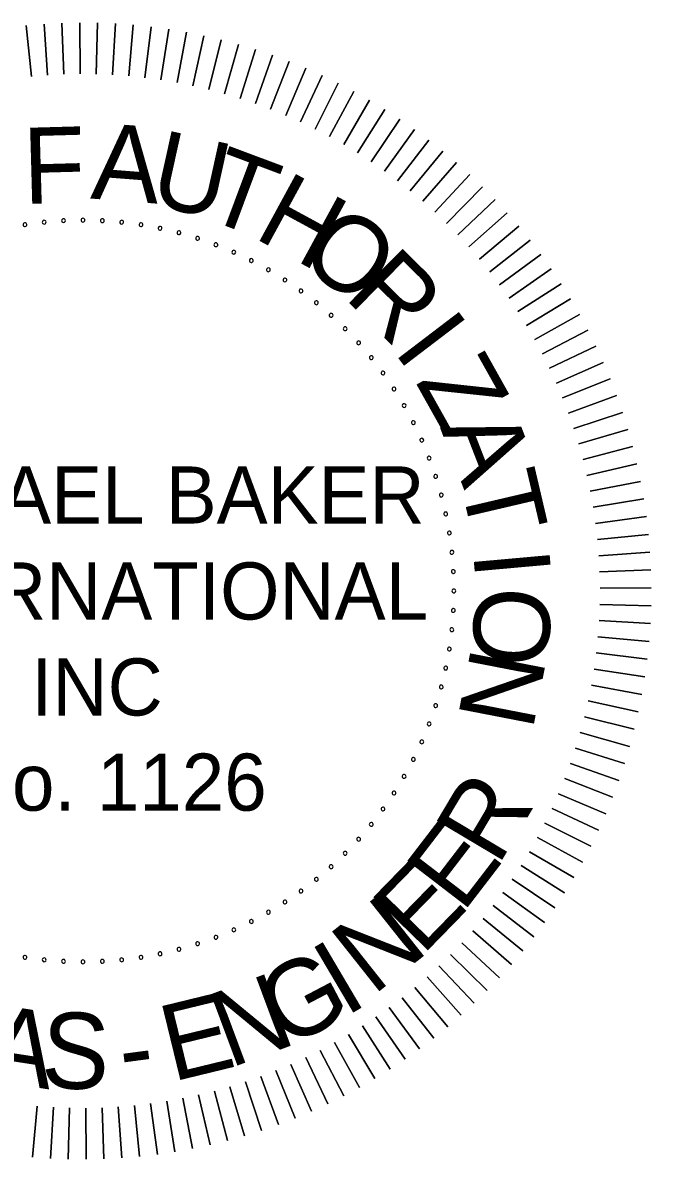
# Model space of a CAD drawing. Extents: x -43543 to 34500, y -13675 to 11152.
# Drawn here: x 7473 to 8849, y -8588 to -6099 of the extents above; entities that cross this region are included whole.
import ezdxf

# ---------------------------------------------------------------- set-up
doc = ezdxf.new("R2010")
doc.units = 0
doc.layers.add('G-ANNO-TEXT', color=7, linetype='Continuous')

msp = doc.modelspace()

# ---------------------------------------------------------------- linework, layer by layer
at = {"layer": 'G-ANNO-TEXT'}
for points in [[(7491.6, -6217.2), (7480.4, -6105.5)], [(7480.4, -6105.5), (7491.6, -6217.2)], [(7527, -6214.2), (7519.4, -6102.2)], [(7519.4, -6102.2), (7527, -6214.2)], [(7562.5, -6212.3), (7558.4, -6100.2)], [(7558.4, -6100.2), (7562.5, -6212.3)], [(7598.1, -6211.6), (7597.5, -6099.4)], [(7597.5, -6099.4), (7598.1, -6211.6)], [(7633.7, -6211.9), (7636.6, -6099.8)], [(7636.6, -6099.8), (7633.7, -6211.9)], [(7669.2, -6213.4), (7675.6, -6101.4)], [(7675.6, -6101.4), (7669.2, -6213.4)], [(7704.7, -6216), (7714.6, -6104.2)], [(7714.6, -6104.2), (7704.7, -6216)], [(7740, -6219.7), (7753.5, -6108.3)], [(7753.5, -6108.3), (7740, -6219.7)], [(7775.3, -6224.5), (7792.2, -6113.6)], [(7792.2, -6113.6), (7775.3, -6224.5)], [(7810.4, -6230.5), (7830.8, -6120.1)], [(7830.8, -6120.1), (7810.4, -6230.5)], [(7845.2, -6237.5), (7869.1, -6127.8)], [(7869.1, -6127.8), (7845.2, -6237.5)], [(7879.9, -6245.6), (7907.2, -6136.7)], [(7907.2, -6136.7), (7879.9, -6245.6)], [(7914.2, -6254.8), (7944.9, -6146.8)], [(7944.9, -6146.8), (7914.2, -6254.8)], [(7948.3, -6265), (7982.4, -6158.1)], [(7982.4, -6158.1), (7948.3, -6265)], [(7982, -6276.4), (8019.4, -6170.6)], [(8019.4, -6170.6), (7982, -6276.4)], [(8015.3, -6288.8), (8056.1, -6184.2)], [(8056.1, -6184.2), (8015.3, -6288.8)], [(8048.3, -6302.2), (8092.3, -6198.9)], [(8092.3, -6198.9), (8048.3, -6302.2)], [(8080.8, -6316.6), (8128, -6214.8)], [(8128, -6214.8), (8080.8, -6316.6)], [(8112.8, -6332.1), (8163.2, -6231.8)], [(8163.2, -6231.8), (8112.8, -6332.1)], [(8144.3, -6348.6), (8197.8, -6249.9)], [(8197.8, -6249.9), (8144.3, -6348.6)], [(8175.3, -6366), (8231.9, -6269.1)], [(8231.9, -6269.1), (8175.3, -6366)], [(8205.7, -6384.4), (8265.3, -6289.4)], [(8265.3, -6289.4), (8205.7, -6384.4)], [(8235.6, -6403.8), (8298.1, -6310.6)], [(8298.1, -6310.6), (8235.6, -6403.8)], [(8264.8, -6424.1), (8330.2, -6332.9)], [(8330.2, -6332.9), (8264.8, -6424.1)], [(8293.3, -6445.3), (8361.6, -6356.2)], [(8361.6, -6356.2), (8293.3, -6445.3)], [(8321.2, -6467.4), (8392.3, -6380.5)], [(8392.3, -6380.5), (8321.2, -6467.4)], [(8348.4, -6490.3), (8422.1, -6405.7)], [(8422.1, -6405.7), (8348.4, -6490.3)], [(8451.2, -6431.9), (8374.8, -6514.1)], [(8374.8, -6514.1), (8451.2, -6431.9)], [(8479.4, -6458.9), (8400.5, -6538.7)], [(8400.5, -6538.7), (8479.4, -6458.9)], [(8506.8, -6486.8), (8425.4, -6564.1)], [(8425.4, -6564.1), (8506.8, -6486.8)], [(8533.3, -6515.6), (8449.5, -6590.3)], [(8449.5, -6590.3), (8533.3, -6515.6)], [(8558.8, -6545.2), (8472.7, -6617.2)], [(8472.7, -6617.2), (8558.8, -6545.2)], [(8583.4, -6575.6), (8495.1, -6644.8)], [(8495.1, -6644.8), (8583.4, -6575.6)], [(8607.1, -6606.7), (8516.6, -6673.2)], [(8516.6, -6673.2), (8607.1, -6606.7)], [(8629.7, -6638.6), (8537.3, -6702.2)], [(8537.3, -6702.2), (8629.7, -6638.6)], [(8651.4, -6671.1), (8556.9, -6731.8)], [(8556.9, -6731.8), (8651.4, -6671.1)], [(8672, -6704.3), (8575.7, -6762)], [(8575.7, -6762), (8672, -6704.3)], [(8691.5, -6738.2), (8593.5, -6792.8)], [(8593.5, -6792.8), (8691.5, -6738.2)], [(8710, -6772.6), (8610.3, -6824.1)], [(8610.3, -6824.1), (8710, -6772.6)], [(8727.4, -6807.6), (8626.1, -6856)], [(8626.1, -6856), (8727.4, -6807.6)], [(8743.7, -6843.2), (8641, -6888.3)], [(8641, -6888.3), (8743.7, -6843.2)], [(8758.9, -6879.2), (8654.7, -6921.1)], [(8654.7, -6921.1), (8758.9, -6879.2)], [(8772.9, -6915.7), (8667.5, -6954.3)], [(8667.5, -6954.3), (8772.9, -6915.7)], [(8785.8, -6952.6), (8679.2, -6987.9)], [(8679.2, -6987.9), (8785.8, -6952.6)], [(8797.5, -6989.9), (8689.9, -7021.8)], [(8689.9, -7021.8), (8797.5, -6989.9)], [(8808, -7027.6), (8699.4, -7056.1)], [(8699.4, -7056.1), (8808, -7027.6)], [(8817.3, -7065.5), (8707.9, -7090.6)], [(8707.9, -7090.6), (8817.3, -7065.5)], [(8825.5, -7103.8), (8715.3, -7125.4)], [(8715.3, -7125.4), (8825.5, -7103.8)], [(8832.4, -7142.2), (8721.7, -7160.4)], [(8721.7, -7160.4), (8832.4, -7142.2)], [(8838.1, -7180.9), (8726.9, -7195.6)], [(8726.9, -7195.6), (8838.1, -7180.9)], [(8842.6, -7219.7), (8731, -7230.9)], [(8731, -7230.9), (8842.6, -7219.7)], [(8845.9, -7258.7), (8733.9, -7266.4)], [(8733.9, -7266.4), (8845.9, -7258.7)], [(8848, -7297.7), (8735.8, -7301.9)], [(8735.8, -7301.9), (8848, -7297.7)], [(8848.8, -7336.8), (8736.6, -7337.4)], [(8736.6, -7337.4), (8848.8, -7336.8)], [(8848.4, -7375.9), (8736.2, -7373)], [(8736.2, -7373), (8848.4, -7375.9)], [(8846.8, -7415), (8734.7, -7408.5)], [(8734.7, -7408.5), (8846.8, -7415)], [(8843.9, -7454), (8732.1, -7444)], [(8732.1, -7444), (8843.9, -7454)], [(8839.9, -7492.8), (8728.4, -7479.4)], [(8728.4, -7479.4), (8839.9, -7492.8)], [(8834.6, -7531.6), (8723.6, -7514.6)], [(8723.6, -7514.6), (8834.6, -7531.6)], [(8828.1, -7570.1), (8717.7, -7549.7)], [(8717.7, -7549.7), (8828.1, -7570.1)], [(8820.3, -7608.4), (8710.7, -7584.6)], [(8710.7, -7584.6), (8820.3, -7608.4)], [(8811.4, -7646.5), (8702.6, -7619.2)], [(8702.6, -7619.2), (8811.4, -7646.5)], [(8801.3, -7684.3), (8693.4, -7653.6)], [(8693.4, -7653.6), (8801.3, -7684.3)], [(8790, -7721.7), (8683.1, -7687.6)], [(8683.1, -7687.6), (8790, -7721.7)], [(8777.6, -7758.7), (8671.8, -7721.3)], [(8671.8, -7721.3), (8777.6, -7758.7)], [(8764, -7795.4), (8659.4, -7754.7)], [(8659.4, -7754.7), (8764, -7795.4)], [(8749.2, -7831.6), (8646, -7787.6)], [(8646, -7787.6), (8749.2, -7831.6)], [(8733.3, -7867.3), (8631.5, -7820.1)], [(8631.5, -7820.1), (8733.3, -7867.3)], [(8716.3, -7902.5), (8616, -7852.1)], [(8616, -7852.1), (8716.3, -7902.5)], [(8698.2, -7937.2), (8599.6, -7883.6)], [(8599.6, -7883.6), (8698.2, -7937.2)], [(8679, -7971.2), (8582.1, -7914.6)], [(8582.1, -7914.6), (8679, -7971.2)], [(8658.8, -8004.7), (8563.7, -7945.1)], [(8563.7, -7945.1), (8658.8, -8004.7)], [(8637.5, -8037.5), (8544.3, -7974.9)], [(8544.3, -7974.9), (8637.5, -8037.5)], [(8615.2, -8069.6), (8524.1, -8004.1)], [(8524.1, -8004.1), (8615.2, -8069.6)], [(8591.9, -8101), (8502.9, -8032.7)], [(8502.9, -8032.7), (8591.9, -8101)], [(8567.6, -8131.6), (8480.8, -8060.6)], [(8480.8, -8060.6), (8567.6, -8131.6)], [(8542.4, -8161.5), (8457.8, -8087.7)], [(8457.8, -8087.7), (8542.4, -8161.5)], [(8516.3, -8190.5), (8434, -8114.2)], [(8434, -8114.2), (8516.3, -8190.5)], [(8489.2, -8218.8), (8409.4, -8139.9)], [(8409.4, -8139.9), (8489.2, -8218.8)], [(8461.3, -8246.1), (8384, -8164.7)], [(8384, -8164.7), (8461.3, -8246.1)], [(8403, -8298.2), (8330.9, -8212.1)], [(8330.9, -8212.1), (8403, -8298.2)], [(8432.5, -8272.6), (8357.9, -8188.8)], [(8357.9, -8188.8), (8432.5, -8272.6)], [(8372.6, -8322.8), (8303.3, -8234.5)], [(8303.3, -8234.5), (8372.6, -8322.8)], [(8341.5, -8346.4), (8275, -8256)], [(8275, -8256), (8341.5, -8346.4)], [(8309.6, -8369.1), (8246, -8276.6)], [(8246, -8276.6), (8309.6, -8369.1)], [(8277, -8390.7), (8216.4, -8296.3)], [(8216.4, -8296.3), (8277, -8390.7)], [(8210, -8430.9), (8155.4, -8332.8)], [(8155.4, -8332.8), (8210, -8430.9)], [(8243.8, -8411.3), (8186.2, -8315)], [(8186.2, -8315), (8243.8, -8411.3)], [(8175.5, -8449.4), (8124, -8349.7)], [(8124, -8349.7), (8175.5, -8449.4)], [(8105, -8483), (8059.8, -8380.3)], [(8059.8, -8380.3), (8105, -8483)], [(8140.5, -8466.8), (8092.2, -8365.5)], [(8092.2, -8365.5), (8140.5, -8466.8)], [(8032.5, -8512.2), (7993.9, -8406.8)], [(7993.9, -8406.8), (8032.5, -8512.2)], [(8068.9, -8498.2), (8027.1, -8394.1)], [(8027.1, -8394.1), (8068.9, -8498.2)], [(7958.2, -8536.8), (7926.3, -8429.2)], [(7926.3, -8429.2), (7958.2, -8536.8)], [(7995.5, -8525.1), (7960.3, -8418.6)], [(7960.3, -8418.6), (7995.5, -8525.1)], [(7805.9, -8571.7), (7787.8, -8461)], [(7787.8, -8461), (7805.9, -8571.7)], [(7844.4, -8564.8), (7822.8, -8454.7)], [(7822.8, -8454.7), (7844.4, -8564.8)], [(7882.6, -8556.7), (7857.5, -8447.3)], [(7857.5, -8447.3), (7882.6, -8556.7)], [(7920.6, -8547.3), (7892.1, -8438.8)], [(7892.1, -8438.8), (7920.6, -8547.3)], [(7494.2, -8583.3), (7504.1, -8471.5)], [(7504.1, -8471.5), (7494.2, -8583.3)], [(7533.2, -8586.1), (7539.6, -8474.1)], [(7539.6, -8474.1), (7533.2, -8586.1)], [(7572.3, -8587.7), (7575.2, -8475.6)], [(7575.2, -8475.6), (7572.3, -8587.7)], [(7611.3, -8588.1), (7610.7, -8475.9)], [(7610.7, -8475.9), (7611.3, -8588.1)], [(7650.4, -8587.3), (7646.3, -8475.2)], [(7646.3, -8475.2), (7650.4, -8587.3)], [(7689.5, -8585.3), (7681.8, -8473.3)], [(7681.8, -8473.3), (7689.5, -8585.3)], [(7728.4, -8582), (7717.2, -8470.3)], [(7717.2, -8470.3), (7728.4, -8582)], [(7767.3, -8577.5), (7752.6, -8466.2)], [(7752.6, -8466.2), (7767.3, -8577.5)]]:
    msp.add_lwpolyline(points, dxfattribs=at)
for centre, start, end in [((7477.4, -6541.6), 9, 189), ((7477.4, -6541.6), 189, 9), ((7519.5, -6536.1), 6, 186), ((7519.5, -6536.1), 186, 6), ((7561.9, -6532.7), 3, 183), ((7561.9, -6532.7), 183, 3), ((7604.4, -6531.6), 0, 180), ((7604.4, -6531.6), 180, 0), ((7646.9, -6532.7), 177, 357), ((7646.9, -6532.7), 357, 177), ((7689.3, -6536.1), 174, 354), ((7689.3, -6536.1), 354, 174), ((7731.5, -6541.6), 351, 171), ((7731.5, -6541.6), 171, 351), ((7773.3, -6549.3), 348, 168), ((7773.3, -6549.3), 168, 348), ((7814.6, -6559.3), 165, 345), ((7814.6, -6559.3), 345, 165), ((7855.4, -6571.4), 162, 342), ((7855.4, -6571.4), 342, 162), ((7895.5, -6585.5), 159, 339), ((7895.5, -6585.5), 339, 159), ((7934.7, -6601.8), 156, 336), ((7934.7, -6601.8), 336, 156), ((7973.1, -6620.1), 153, 333), ((7973.1, -6620.1), 333, 153), ((8010.5, -6640.4), 150, 330), ((8010.5, -6640.4), 330, 150), ((8046.7, -6662.6), 147, 327), ((8046.7, -6662.6), 327, 147), ((8081.8, -6686.7), 144, 324), ((8081.8, -6686.7), 324, 144), ((8115.5, -6712.6), 141, 321), ((8115.5, -6712.6), 321, 141), ((8147.8, -6740.2), 138, 318), ((8147.8, -6740.2), 318, 138), ((8178.7, -6769.5), 135, 315), ((8178.7, -6769.5), 315, 135), ((8208, -6800.3), 132, 312), ((8208, -6800.3), 312, 132), ((8235.6, -6832.6), 129, 309), ((8235.6, -6832.6), 309, 129), ((8261.4, -6866.4), 126, 306), ((8261.4, -6866.4), 306, 126), ((8285.5, -6901.4), 123, 303), ((8285.5, -6901.4), 303, 123), ((8307.7, -6937.7), 120, 300), ((8307.7, -6937.7), 300, 120), ((8328, -6975), 117, 297), ((8328, -6975), 297, 117), ((8346.3, -7013.4), 114, 294), ((8346.3, -7013.4), 294, 114), ((8362.6, -7052.7), 111, 291), ((8362.6, -7052.7), 291, 111), ((8376.8, -7092.8), 108, 288), ((8376.8, -7092.8), 288, 108), ((8388.9, -7133.6), 105, 285), ((8388.9, -7133.6), 285, 105), ((8398.8, -7174.9), 102, 282), ((8398.8, -7174.9), 282, 102), ((8406.6, -7216.7), 99, 279), ((8406.6, -7216.7), 279, 99), ((8412.1, -7258.9), 96, 276), ((8412.1, -7258.9), 276, 96), ((8415.4, -7301.2), 93, 273), ((8415.4, -7301.2), 273, 93), ((8416.6, -7343.7), 90, 270), ((8416.6, -7343.7), 270, 90), ((8415.4, -7386.3), 87, 267), ((8415.4, -7386.3), 267, 87), ((8412.1, -7428.6), 84, 264), ((8412.1, -7428.6), 264, 84), ((8406.6, -7470.8), 81, 261), ((8406.6, -7470.8), 261, 81), ((8398.8, -7512.6), 78, 258), ((8398.8, -7512.6), 258, 78), ((8388.9, -7553.9), 75, 255), ((8388.9, -7553.9), 255, 75), ((8376.8, -7594.7), 72, 252), ((8376.8, -7594.7), 252, 72), ((8362.6, -7634.8), 69, 249), ((8362.6, -7634.8), 249, 69), ((8346.3, -7674.1), 66, 246), ((8346.3, -7674.1), 246, 66), ((8328, -7712.5), 63, 243), ((8328, -7712.5), 243, 63), ((8307.7, -7749.8), 60, 240), ((8307.7, -7749.8), 240, 60), ((8285.5, -7786.1), 57, 237), ((8285.5, -7786.1), 237, 57), ((8261.4, -7821.1), 54, 234), ((8261.4, -7821.1), 234, 54), ((8235.6, -7854.9), 51, 231), ((8235.6, -7854.9), 231, 51), ((8208, -7887.2), 48, 228), ((8208, -7887.2), 228, 48), ((8178.7, -7918), 45, 225), ((8178.7, -7918), 225, 45), ((8147.8, -7947.3), 42, 222), ((8147.8, -7947.3), 222, 42), ((8115.5, -7974.9), 39, 219), ((8115.5, -7974.9), 219, 39), ((8081.8, -8000.8), 36, 216), ((8081.8, -8000.8), 216, 36), ((8046.7, -8024.9), 33, 213), ((8046.7, -8024.9), 213, 33), ((7973.1, -8067.4), 27, 207), ((8010.5, -8047.1), 30, 210), ((8010.5, -8047.1), 210, 30), ((7934.7, -8085.7), 24, 204), ((7934.7, -8085.7), 204, 24), ((7973.1, -8067.4), 207, 27), ((7855.4, -8116.1), 18, 198), ((7895.5, -8102), 21, 201), ((7895.5, -8102), 201, 21), ((7773.3, -8138.2), 12, 192), ((7773.3, -8138.2), 192, 12), ((7814.6, -8128.2), 15, 195), ((7814.6, -8128.2), 195, 15), ((7855.4, -8116.1), 198, 18), ((7477.4, -8145.9), 351, 171), ((7477.4, -8145.9), 171, 351), ((7519.5, -8151.4), 174, 354), ((7519.5, -8151.4), 354, 174), ((7561.9, -8154.8), 357, 177), ((7561.9, -8154.8), 177, 357), ((7604.4, -8155.9), 0, 180), ((7604.4, -8155.9), 180, 0), ((7646.9, -8154.8), 3, 183), ((7646.9, -8154.8), 183, 3), ((7689.3, -8151.4), 6, 186), ((7689.3, -8151.4), 186, 6), ((7731.5, -8145.9), 9, 189), ((7731.5, -8145.9), 189, 9)]:
    msp.add_arc(centre, 4.17, start, end, dxfattribs=at)

# ---------------------------------------------------------------- texts
for s, rotation, p in [('F', 1.5867, (7475.1, -6496.4)), ('A', 355.5955, (7619.6, -6484.2)), ('U', 347.5481, (7745.7, -6496.1)), ('T', 339.5007, (7862.1, -6523.9)), ('H', 331.4533, (7975.1, -6568.4)), ('O', 323.4059, (8070.8, -6621.1)), ('R', 315.3585, (8174.1, -6700.2)), ('I', 307.3112, (8282.4, -6817.6)), ('Z', 299.2638, (8331.4, -6885.5)), ('A', 291.2164, (8386, -6985.7)), ('T', 283.169, (8429.6, -7103.7)), ('I', 275.1216, (8458.5, -7259.6)), ('O', 267.0743, (8464.4, -7331.3)), ('N', 259.0269, (8455.6, -7462.3)), ('R', 59.2262, (8513.1, -7948.2)), ('E', 52.4765, (8435.7, -8050.8)), ('E', 45.7268, (8346.9, -8143.6)), ('N', 38.4196, (8239.1, -8231.5)), ('I', 30.5495, (8178.6, -8277.4)), ('G', 27.7404, (8046.8, -8347.4)), ('N', 20.4332, (7925.5, -8389.4)), ('E', 13.6835, (7799.9, -8418.8)), ('A', 351.1991, (7383.9, -8412.6)), ('S', 357.9489, (7511, -8431.1)), ('-', 7.5077, (7692.9, -8431.5))]:
    msp.add_text(s, height=166.7, rotation=rotation, dxfattribs=at).set_placement(p)
for s, height, p in [('MICHAEL BAKER', 125.016, (6996.1, -7196)), (' INTERNATIONAL', 125.016, (6976, -7406.2)), ('INC', 125.02, (7491.2, -7616.4)), (' No. 1126', 125.02, (7281.8, -7824.8))]:
    msp.add_text(s, height=height, dxfattribs=at).set_placement(p)

doc.saveas('drawing.dxf')
